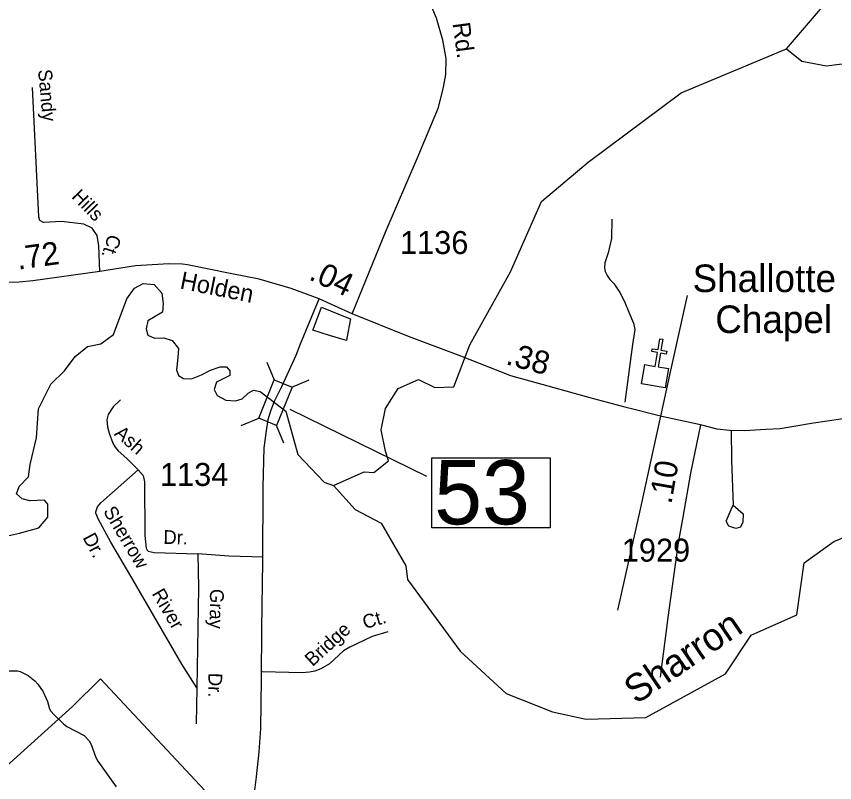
# Model space of a CAD drawing. Extents: x 2104537 to 2336408, y 34176 to 229611.
# Drawn here: x 2193201 to 2197655, y 81004 to 85176 of the extents above; entities that cross this region are included whole.
import ezdxf

# ---------------------------------------------------------------- set-up
doc = ezdxf.new("R2010")
doc.units = 0
for name, color, linetype in [('Exist Boundary Political City Limit New', 7, 'Continuous'), ('Exist Cultural Church CELL', 7, 'Continuous'), ('Exist Cultural Church Label', 7, 'Continuous'), ('Exist Hydrographic Creek Single Shore', 7, 'Continuous'), ('Exist Road Non-System Type 51', 7, 'Continuous'), ('Exist Road Non-System Type 51 Label', 7, 'Continuous'), ('Exist Road Primary NC Attributed', 7, 'Continuous'), ('Exist Road Primary NC Label', 7, 'Continuous'), ('Exist Road Primary NC Mileage Hundredths English Label', 7, 'Continuous'), ('Exist Road Secondary Mileage Hundredths English Label', 7, 'Continuous'), ('Exist Road Secondary Structure Private Number Label', 7, 'Continuous'), ('Exist Road Secondary Type 51 Attributed', 7, 'Continuous'), ('Exist Road Secondary Type 51 Label', 7, 'Continuous'), ('Exist Road Secondary Type 51 Number Label', 7, 'Continuous'), ('Exist Road State Agency Structure Standard Bridge CELL', 7, 'Continuous'), ('Map Preparation Boundary City Limit Buffer Line', 7, 'Continuous'), ('Old_Level_32', 7, 'Continuous')]:
    doc.layers.add(name, color=color, linetype=linetype)

msp = doc.modelspace()

# ---------------------------------------------------------------- linework, layer by layer
at = {"layer": 'Exist Boundary Political City Limit New'}
for points in [[(2195000, 83423.2), (2194997.8, 83411.4), (2194984.8, 83415.3), (2194905, 83438.8), (2194814.5, 83466.8), (2194816.2, 83471.3), (2194862, 83592), (2195000, 83536.9), (2195020, 83529), (2195000, 83423.2)], [(2193128.8, 81077.5), (2193506.8, 81417.8), (2193658, 81569)], [(2193658, 81569), (2194380.5, 80796.1)]]:
    msp.add_lwpolyline(points, dxfattribs=at)
at = {"layer": 'Exist Cultural Church CELL'}
msp.add_lwpolyline([(2196622.1, 83279.9), (2196678.2, 83270.4), (2196691, 83345.5), (2196659.5, 83350.9), (2196662.2, 83366.6), (2196693.7, 83361.3), (2196703.8, 83420.5), (2196719.6, 83417.9), (2196709.5, 83358.6), (2196741.1, 83353.2), (2196738.4, 83337.4), (2196706.8, 83342.8), (2196694, 83267.8), (2196750.9, 83258), (2196733, 83153), (2196604.2, 83175)], close=True, dxfattribs=at)
at = {"layer": 'Exist Hydrographic Creek Single Shore'}
for points in [[(2197393.7, 84998.8), (2197476.7, 84931.5), (2197610.6, 84906), (2197893.6, 84943.1), (2198076.7, 85044.6), (2198448.7, 85437.7), (2198597.8, 85530), (2198946.8, 85631.5), (2199129.7, 85769), (2199418.8, 86084.9), (2199707.7, 86437), (2199831.8, 86638), (2200086.6, 87197.4), (2200225.7, 87450.6), (2200663.7, 88062.1), (2200770.7, 88220.8), (2200985.8, 88456.2)], [(2197393.7, 84998.8), (2197599.8, 85240.8), (2197608.8, 85283.3)], [(2194926.7, 82621.9), (2195094.5, 82695.5), (2195146.2, 82692.7), (2195226.6, 82755.9), (2195209.4, 82807.6), (2195186.4, 82925.5), (2195209.4, 83040.5), (2195278.4, 83149.7), (2195390.4, 83198.6), (2195479.5, 83155.5), (2195582.9, 83158.4), (2195669.1, 83388.3), (2195890.3, 83785), (2196059.8, 84167.4), (2196312.6, 84383), (2196819.8, 84760.5), (2197393.7, 84998.8)], [(2193085.9, 82333.4), (2193217.4, 82362.3), (2193323.2, 82391.2), (2193371.3, 82448.9), (2193371.3, 82519.5), (2193353.7, 82542), (2193273.5, 82538.8), (2193231.8, 82548.4), (2193201.4, 82575.6), (2193215.8, 82615.7), (2193267.1, 82668.7), (2193276.7, 82735.8), (2193310.4, 82882), (2193321.6, 83039.2), (2193388.9, 83174), (2193462.7, 83246.1), (2193520.4, 83324.7), (2193587.7, 83377.7), (2193659.9, 83392.1), (2193730.4, 83443.4), (2193802.5, 83637.5), (2193844.2, 83696.9), (2193890.7, 83720.9), (2193951.6, 83716.1), (2193993.3, 83669.6), (2193999.7, 83613.5), (2193995.6, 83565.1), (2193916.4, 83518.8), (2193906.7, 83475.5), (2193916.4, 83440.2), (2193953.2, 83424.2), (2194004.5, 83425.8), (2194049.4, 83411.4), (2194083.1, 83368), (2194079.9, 83318.3), (2194071.9, 83251), (2194083.1, 83220.5), (2194110.3, 83204.4), (2194153.6, 83202.8), (2194208.1, 83223.7), (2194257.8, 83249.3), (2194310.7, 83268.6), (2194344.4, 83267), (2194363.6, 83246.1), (2194363.6, 83220.5), (2194289.9, 83183.6), (2194277.1, 83143.5), (2194294.7, 83111.4), (2194341.2, 83085.7), (2194394.1, 83082.5), (2194429.4, 83093.8), (2194463, 83124.2), (2194491.1, 83141.1), (2194528.7, 83133.9), (2194668.2, 83026.4), (2194733.8, 82789.6), (2194876.7, 82639.3), (2194926.7, 82621.9)], [(2194926.7, 82621.9), (2195044.6, 82491.7), (2195186.7, 82416.8), (2195321.6, 82184.5), (2195330.7, 82108.9), (2195616.7, 81719.5), (2195867.7, 81488.2), (2196118.7, 81388.2), (2196301.8, 81348.6), (2196626.8, 81358.8), (2197060.2, 81596), (2197201.6, 81806.1), (2197450.1, 81917.6), (2197488.7, 82200.5), (2197651.5, 82316.3), (2197912.9, 82423.4)]]:
    msp.add_lwpolyline(points, dxfattribs=at)
at = {"layer": 'Exist Road Non-System Type 51'}
msp.add_line((2194183, 81519.1), (2194179.6, 81323), dxfattribs=at)
for points in [[(2193655.3, 83786.5), (2193650.1, 83926.7), (2193639.9, 83982.8), (2193614.4, 84023.5), (2193568.6, 84043.9), (2193446.3, 84059.2), (2193349.5, 84054.1), (2193329.2, 84064.3), (2193324.1, 84084.7), (2193288.4, 84788)], [(2196442.5, 84071), (2196441.3, 83966.7), (2196422.2, 83888.9), (2196404.2, 83833.8), (2196401.8, 83807.4), (2196405.4, 83787), (2196417.4, 83764.3), (2196430.6, 83743.9), (2196453, 83721.6), (2196485.6, 83672.7), (2196511.7, 83623.7), (2196534.5, 83565), (2196560.6, 83506.3), (2196567.2, 83470.4), (2196554.1, 83388.8), (2196513.2, 83075.5)], [(2196851.9, 83655.5), (2196765.2, 83264.7), (2196707.6, 82998.4)], [(2193768.1, 83087.8), (2193728.6, 83049.2), (2193701.3, 83009), (2193693.5, 82980), (2193696.7, 82940.9), (2193706.2, 82906.3), (2193726.8, 82852.7), (2193739.5, 82829.5), (2193755.8, 82809.5), (2193802.6, 82768.2), (2193863.4, 82707)], [(2196707.6, 82998.4), (2196663.9, 82800.7), (2196596.1, 82491.9), (2196474, 81942.3)], [(2197092, 82920.4), (2197092.9, 82758.8), (2197102.1, 82515.3)], [(2194183, 81519.1), (2194101.2, 81648), (2193837.1, 82106.8), (2193714.4, 82312.9), (2193648.2, 82436.9), (2193633.8, 82470), (2193633.3, 82477.5), (2193641.7, 82505.9), (2193661.5, 82526.5), (2193863.4, 82707)], [(2193863.4, 82707), (2193891.7, 82675.3), (2193898.9, 82642), (2193899.8, 82349.4), (2193906.7, 82279.4), (2193912.7, 82269.7), (2193919.2, 82263.7), (2193951.2, 82256.2), (2194189.6, 82249.3)], [(2197102.1, 82515.3), (2197156.3, 82466.4), (2197155, 82421.4), (2197141.8, 82395), (2197118, 82387), (2197079.7, 82400.2), (2197063.8, 82428), (2197086.3, 82478.1), (2197091.6, 82491.5), (2197102.1, 82515.3)], [(2196828.3, 82448.4), (2196803.4, 82310.1), (2196746.5, 81903.4), (2196705.9, 81578)], [(2194189.6, 82249.3), (2194191.6, 82065.2), (2194183, 81519.1)], [(2194543.6, 82232), (2194357.6, 82237.5), (2194189.6, 82249.3)], [(2195223.3, 81824.5), (2195137.6, 81799.2), (2195016.4, 81741.2), (2194982.5, 81721.2), (2194905.4, 81650.5), (2194857.6, 81623.9), (2194825.9, 81611.4), (2194795.9, 81605), (2194756.1, 81600.6), (2194539.7, 81607.7)], [(2193087.4, 81613.1), (2193207.5, 81612.4), (2193221.5, 81608.9), (2193265.7, 81587), (2193301.6, 81558.1), (2193318.3, 81539.7), (2193347, 81498.2), (2193369.6, 81444.6), (2193381.6, 81406), (2193389.2, 81392.7), (2193406.6, 81373), (2193456.8, 81323.5), (2193475.6, 81310), (2193570.1, 81259.9), (2193596.4, 81231.6), (2193608.8, 81211.6), (2193633.7, 81140), (2193643.8, 81119.7), (2193743.8, 80981.3)]]:
    msp.add_lwpolyline(points, dxfattribs=at)
at = {"layer": 'Exist Road Primary NC Attributed'}
for points in [[(2194849.6, 83637.8), (2194696.2, 83694.5), (2194522.5, 83746), (2194365.4, 83775.7), (2194132.7, 83822.5), (2194104.5, 83826.4), (2194030.5, 83829.4), (2193848.8, 83816.9), (2193655.3, 83786.5), (2193291.1, 83736.4), (2193216.6, 83729.5), (2193088.2, 83724.5)], [(2195028.7, 83556.1), (2194932.9, 83599), (2194849.6, 83637.8)], [(2196924.4, 82951.6), (2196713.8, 82997.1), (2196526.7, 83044.8), (2196337.7, 83094.4), (2196094.9, 83163.2), (2195892.6, 83218.6), (2195612, 83329.3), (2195335.2, 83432.5), (2195028.7, 83556.1)], [(2198910, 82840.3), (2198792.8, 82897.7), (2198670.7, 82947.4), (2198575.2, 82981.8), (2198495.1, 83000.9), (2198424.4, 83016.1), (2198332.8, 83029.5), (2198244.2, 83056.3), (2198140, 83037.2), (2198021.7, 83031.4), (2197916.7, 83020), (2197764, 82993.2), (2197540.7, 82960.8), (2197359.3, 82930.2), (2197281.1, 82926.4), (2197164.3, 82918.8), (2197082.2, 82920.7), (2197015.4, 82928.3), (2196924.4, 82951.6)]]:
    msp.add_lwpolyline(points, dxfattribs=at)
at = {"layer": 'Exist Road Secondary Structure Private Number Label'}
msp.add_line((2194688.7, 83038.1), (2195434, 82672.8), dxfattribs=at)
msp.add_lwpolyline([(2195463.2, 82772.6), (2196107.3, 82772.6), (2196107.3, 82390.3), (2195463.2, 82390.3)], close=True, dxfattribs=at)
at = {"layer": 'Exist Road Secondary Type 51 Attributed'}
for points in [[(2195028.7, 83556.1), (2195214.4, 84010.3), (2195382.3, 84403), (2195499.3, 84680.2), (2195526.5, 84791.3), (2195538.8, 84860.5), (2195541.3, 84946.9), (2195521.6, 85045.7), (2195487, 85166.8), (2195442.6, 85275.5)], [(2194606.6, 83081.3), (2194612.4, 83094.8), (2194645.5, 83161.1), (2194723.3, 83332.1), (2194748.4, 83393), (2194849.6, 83637.8)], [(2194495.5, 80933.7), (2194507.8, 81034.9), (2194522.6, 81170.8), (2194532.5, 81299.2), (2194535, 81568.5), (2194537.5, 81842.6), (2194542.4, 82207.2), (2194544.9, 82612.3), (2194549.8, 82827.2), (2194562.1, 82918.6), (2194572, 82980.3), (2194587.2, 83032.7), (2194606.6, 83081.3)], [(2196924.4, 82951.6), (2196870.7, 82688.7), (2196828.3, 82448.4)]]:
    msp.add_lwpolyline(points, dxfattribs=at)
at = {"layer": 'Exist Road State Agency Structure Standard Bridge CELL'}
for p, q in [((2194605.5, 83195.9), (2194565.7, 83290.8)), ((2194700.8, 83157), (2194795.6, 83196.9)), ((2194425, 82947.6), (2194519.9, 82987.5)), ((2194657.2, 82852.8), (2194617.3, 82947.7))]:
    msp.add_line(p, q, dxfattribs=at)
msp.add_lwpolyline([(2194519.9, 82987.5), (2194605.1, 83196.1), (2194702.5, 83156.3), (2194617.3, 82947.7)], close=True, dxfattribs=at)
at = {"layer": 'Map Preparation Boundary City Limit Buffer Line'}
for points in [[(2195000, 83423.2), (2194997.8, 83411.4), (2194984.8, 83415.3), (2194905, 83438.8), (2194814.5, 83466.8), (2194816.2, 83471.3), (2194862, 83592), (2195000, 83536.9), (2195020, 83529), (2195000, 83423.2)], [(2193128.8, 81077.5), (2193506.8, 81417.8), (2193658, 81569)], [(2193658, 81569), (2194380.5, 80796.1)]]:
    msp.add_lwpolyline(points, dxfattribs=at)

# ---------------------------------------------------------------- texts
at = {"layer": 'Exist Cultural Church Label'}
for s, p in [('Shallotte', (2196882, 83674.9)), ('Chapel', (2197005.4, 83451.8))]:
    msp.add_text(s, height=150, dxfattribs=at).set_placement(p)
at = {"layer": 'Exist Road Non-System Type 51 Label'}
for s, rotation, p in [('Sandy ', 275.0578, (2193319, 84885)), ('Hills', 314.163, (2193497, 84190.6)), ('Ct.', 251.6135, (2193703.3, 83994.2)), ('Ash', 318.585, (2193729.6, 82898.3)), ('Sherrow', 300.7584, (2193671.4, 82481.5)), ('Dr.', 298.0912, (2193560.2, 82338.1)), ('Dr.', 358.3421, (2194000.4, 82304)), ('River', 299.9243, (2193936.3, 82033.2)), ('Gray', 269.0998, (2194255.5, 82058.9)), ('Ct.', 16.3984, (2195098, 81838.9)), ('Bridge', 42.4954, (2194813, 81632.7)), ('Dr.', 269.0999, (2194247, 81601.5))]:
    msp.add_text(s, height=75, rotation=rotation, dxfattribs=at).set_placement(p)
at = {"layer": 'Exist Road Primary NC Label'}
msp.add_text('Holden', height=95, rotation=348.6239, dxfattribs=at).set_placement((2194086.8, 83695.1))
at = {"layer": 'Exist Road Primary NC Mileage Hundredths English Label'}
for s, rotation, p in [('.72', 7.8262, (2193210.6, 83796.5)), ('.04', 335.0247, (2194787.5, 83745.8)), ('.38', 344.6927, (2195860.1, 83283))]:
    msp.add_text(s, height=125, rotation=rotation, dxfattribs=at).set_placement(p)
at = {"layer": 'Exist Road Secondary Mileage Hundredths English Label'}
msp.add_text('.10', height=125, rotation=79.9875, dxfattribs=at).set_placement((2196766, 82516.6))
at = {"layer": 'Exist Road Secondary Structure Private Number Label'}
msp.add_text('53', height=350, dxfattribs=at).set_placement((2195475.7, 82410.1))
at = {"layer": 'Exist Road Secondary Type 51 Label'}
msp.add_text('Rd.', height=95, rotation=277.7933, dxfattribs=at).set_placement((2195574.9, 85138.1))
at = {"layer": 'Exist Road Secondary Type 51 Number Label'}
for s, p in [('1136', (2195289.4, 83882.2)), ('1134', (2193982.8, 82619.2)), ('1929', (2196496.6, 82206.9))]:
    msp.add_text(s, height=125, dxfattribs=at).set_placement(p)
at = {"layer": 'Old_Level_32'}
msp.add_text('Sharron', height=150, rotation=34.135, dxfattribs=at).set_placement((2196574.9, 81426.9))

doc.saveas('drawing.dxf')
